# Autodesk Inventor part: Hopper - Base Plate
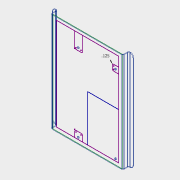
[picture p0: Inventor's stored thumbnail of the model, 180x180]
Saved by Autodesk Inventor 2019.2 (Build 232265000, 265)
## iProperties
Created: 2005-11
Part Number: Hopper - Base Plate
Document SubType Name: Sheet Metal
Designer: floress
Material: Aluminum 6061
Density: 2.7 g/cm^3
Sheet Metal Rule: Default
Appearance: Aluminum - Flat
Flat Pattern Width: 18.4948 cm
Flat Pattern Length: 20.32 cm
Flat Pattern Area: 375.815 cm^2
Sheet Metal Width: 7.281 in
Sheet Metal Length: 8.000 in
Sheet Metal Area: 58.251 in^2
Author: floress
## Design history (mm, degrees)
node "Face1"
  sketch "Sketch1"
    geometry: L1 (-72.35, 101.6)-(72.35, 101.6); L2 (72.35, 101.6)-(72.35, -101.6); L3 (72.35, -101.6)-(-72.35, -101.6); L4 (-72.35, -101.6)-(-72.35, 101.6); 3 further points
    constraints: 8 end point, 2 midpoint, 2 parallel, 1 horizontal, 1 horizontal alignment, 1 perpendicular, 1 vertical alignment
    dimensions: "d0" = 144.7 distance of L2.end L3.end; "d1" = 203.2 distance of L3.end L1.start
node "Flange1"
node "Flange2"
node "Flange3"
node "Flange4"
sketch "Sketch6"
  geometry: L1 (-141.525, 203.2)-(0, 203.2) reference; 4 further points
  dimensions: "d38" = 32.60125 distance from line of L1 point (-12.7, 170.599); "d39" = 32.60125 distance from line of L1 point (-88.9, 170.599); "d40" = 158.88537 distance of point (-12.7, 11.713) point (-12.7, 170.599); "d41" = 158.88537 distance of point (-88.9, 11.713) point (-88.9, 170.599)
hole "Hole1" sketch "Sketch6" at (-12.7, 170.599), (-88.9, 170.599), (-88.9, 11.713), (-12.7, 11.713) diameter "d31" = 3.302; stored, may be unused: countersink angle "d35" = 82 deg, drill point angle "d37" = 118 deg; dims "d32" = 12.7, "d33" = 9.525, "d34" = 6.35, "d36" = 1.5875 (= Thickness)
feature "Corner Round1" dims "d42" = 6.35
sketch "Sketch7"
  geometry: L1 (-70.763, 101.6)-(70.763, 101.6) reference; L2 (70.763, -101.6)-(70.763, 101.6) reference; L3 (70.763, -101.6)-(-70.762, -101.6) reference; L4 (-70.763, 101.6)-(-70.762, -101.6) reference; L5 (-63.757, -94.595)-(63.757, -94.595); L6 (63.757, -94.595)-(63.757, 94.595); L7 (63.757, 94.595)-(-63.757, 94.595); L8 (-63.757, 94.595)-(-63.757, -94.595); L9 (63.757, 75.154)-(53.564, 75.154); L10 (50.389, 71.979)-(50.389, 66.109); L11 (53.564, 62.934)-(63.757, 62.934); L12 (63.757, 62.934)-(63.757, 75.154); L13 (-10.166, 94.595)-(-26.516, 94.595); L14 (-26.516, 94.595)-(-26.516, 66.109); L15 (-23.341, 62.934)-(-13.341, 62.934); L16 (-10.166, 66.109)-(-10.166, 94.595); L17 (-10.166, -94.595)-(-26.516, -94.595); L18 (-26.516, -94.595)-(-26.516, -83.757); L19 (-23.341, -80.582)-(-13.341, -80.582); L20 (-10.166, -83.757)-(-10.166, -94.595); L21 (63.757, 0)-(-18.137, 0); L22 (-18.137, 0)-(-18.341, -80.582); A1 r 3.175 centre (53.564, 71.979) between (53.564, 75.154) and (50.389, 71.979); A2 r 3.175 centre (53.564, 66.109) between (50.389, 66.109) and (53.564, 62.934); A3 r 3.175 centre (-13.341, -83.757) between (-10.166, -83.757) and (-13.341, -80.582); A4 r 3.175 centre (-23.341, -83.757) between (-23.341, -80.582) and (-26.516, -83.757); A5 r 3.175 centre (-13.341, 66.109) between (-13.341, 62.934) and (-10.166, 66.109); A6 r 3.175 centre (-23.341, 66.109) between (-26.516, 66.109) and (-23.341, 62.934); 3 further points
  constraints: 36 end point, 12 point on circle, 12 tangent, 10 point on line, 6 centre point, 6 parallel, 5 equal radius, 4 horizontal, 3 perpendicular, 2 midpoint, 3 other
  dimensions: "d44" = 3.175 radius of A1 (derived)
cut "Cut1" sketch "Sketch7" dims "d45" = 1.5875 (= Thickness), "d46" = 0
body "Solid1"
face "Plate1" dims "d43" = 1.5875 (= Thickness)
sketch "Sketch2"
  geometry: L1 through (-101.6, 0) direction (-1, 0); L2 (-203.2, 0)-(-203.2, -12); L3 (-203.2, -12)-(0, -12); L4 through (0, -6) direction (0, 1)
  constraints: 6 end point, 1 horizontal, 1 perpendicular, 1 vertical
face "Plate2" dims "d3" = 1.5875 (= BendReliefWidth), "d5" = 3.175 (= MinimumRemnant), "d7" = 12, "d8" = 90 deg, "d9" = 1.5875 (= BendRadius), "d43" = 1.5875 (= Thickness)
bend "Bend1" dims "d3" = 1.5875 (= BendReliefWidth), "d4" = 0.79375 (= BendReliefDepth), "d5" = 3.175 (= MinimumRemnant), "d6" = 1.5875 (= BendRadius), "d7" = 12, "d8" = 90 deg, "d9" = 1.5875 (= BendRadius), "d43" = 1.5875 (= Thickness), "SeamGap" = 0.00508
sketch "Sketch3"
  geometry: L1 through (-101.6, 0) direction (-1, 0); L2 (-203.2, 0)-(-203.2, -12); L3 (-203.2, -12)-(0, -12); L4 through (0, -6) direction (0, 1)
  constraints: 6 end point, 1 horizontal, 1 perpendicular, 1 vertical
face "Plate3" dims "d10" = 1.5875 (= BendReliefWidth), "d12" = 3.175 (= MinimumRemnant), "d14" = 12, "d15" = 90 deg, "d16" = 1.5875 (= BendRadius), "d43" = 1.5875 (= Thickness)
bend "Bend2" dims "d10" = 1.5875 (= BendReliefWidth), "d11" = 0.79375 (= BendReliefDepth), "d12" = 3.175 (= MinimumRemnant), "d13" = 1.5875 (= BendRadius), "d14" = 12, "d15" = 90 deg, "d16" = 1.5875 (= BendRadius), "d43" = 1.5875 (= Thickness), "SeamGap" = 0.00508
sketch "Sketch4"
  geometry: L1 through (0, -101.6) direction (0, -1); L2 (0, -203.2)-(8.88, -203.2); L3 (8.88, -203.2)-(8.88, 0); L4 through (4.44, 0) direction (-1, -9.64e-64)
  constraints: 6 end point, 1 horizontal, 1 perpendicular, 1 vertical
face "Plate4" dims "d17" = 1.5875 (= BendReliefWidth), "d19" = 3.175 (= MinimumRemnant), "d21" = 8.88, "d22" = 90 deg, "d23" = 1.5875 (= BendRadius), "d43" = 1.5875 (= Thickness)
bend "Bend3" dims "d17" = 1.5875 (= BendReliefWidth), "d18" = 0.79375 (= BendReliefDepth), "d19" = 3.175 (= MinimumRemnant), "d20" = 1.5875 (= BendRadius), "d21" = 8.88, "d22" = 90 deg, "d23" = 1.5875 (= BendRadius), "d43" = 1.5875 (= Thickness), "SeamGap" = 0.00508
sketch "Sketch5"
  geometry: L1 through (0, 101.6) direction (-8.74e-17, 1); L2 (0, 203.2)-(-8.88, 203.2); L3 (-8.88, 203.2)-(-8.88, 0); L4 through (-4.44, 0) direction (1, -3.2e-34)
  constraints: 6 end point, 1 horizontal, 1 perpendicular, 1 vertical
face "Plate5" dims "d24" = 1.5875 (= BendReliefWidth), "d26" = 3.175 (= MinimumRemnant), "d28" = 8.88, "d29" = 90 deg, "d30" = 1.5875 (= BendRadius), "d43" = 1.5875 (= Thickness)
bend "Bend4" dims "d24" = 1.5875 (= BendReliefWidth), "d25" = 0.79375 (= BendReliefDepth), "d26" = 3.175 (= MinimumRemnant), "d27" = 1.5875 (= BendRadius), "d28" = 8.88, "d29" = 90 deg, "d30" = 1.5875 (= BendRadius), "d43" = 1.5875 (= Thickness), "SeamGap" = 0.00508
feature "Definition1"
other parameters: "Thickness" = 1.5875 (derived), "BendRadius" = 1.5875 (= Thickness), "BendReliefWidth" = 1.5875 (= Thickness), "BendReliefDepth" = 0.79375 (= 0.5 x Thickness), "CornerReliefSize" = 6.35 (= 4 x Thickness), "MinimumRemnant" = 3.175 (= 2 x Thickness), "TransitionRadius" = 1.5875 (= BendRadius), "d2" = 1.5875 (= BendRadius), "JacobiRadiusSize" = 1.5875 (= Thickness), "GapSize" = 1.5875 (= Thickness), "BendRadius" = 1.5875, "BendReliefDepth" = 0.79375, "BendReliefWidth" = 1.5875, "CornerReliefSize" = 6.35, "GapSize" = 1.5875, "JacobiRadiusSize" = 1.5875, "MinimumRemnant" = 3.175, "Thickness" = 1.5875, "TransitionRadius" = 1.5875
